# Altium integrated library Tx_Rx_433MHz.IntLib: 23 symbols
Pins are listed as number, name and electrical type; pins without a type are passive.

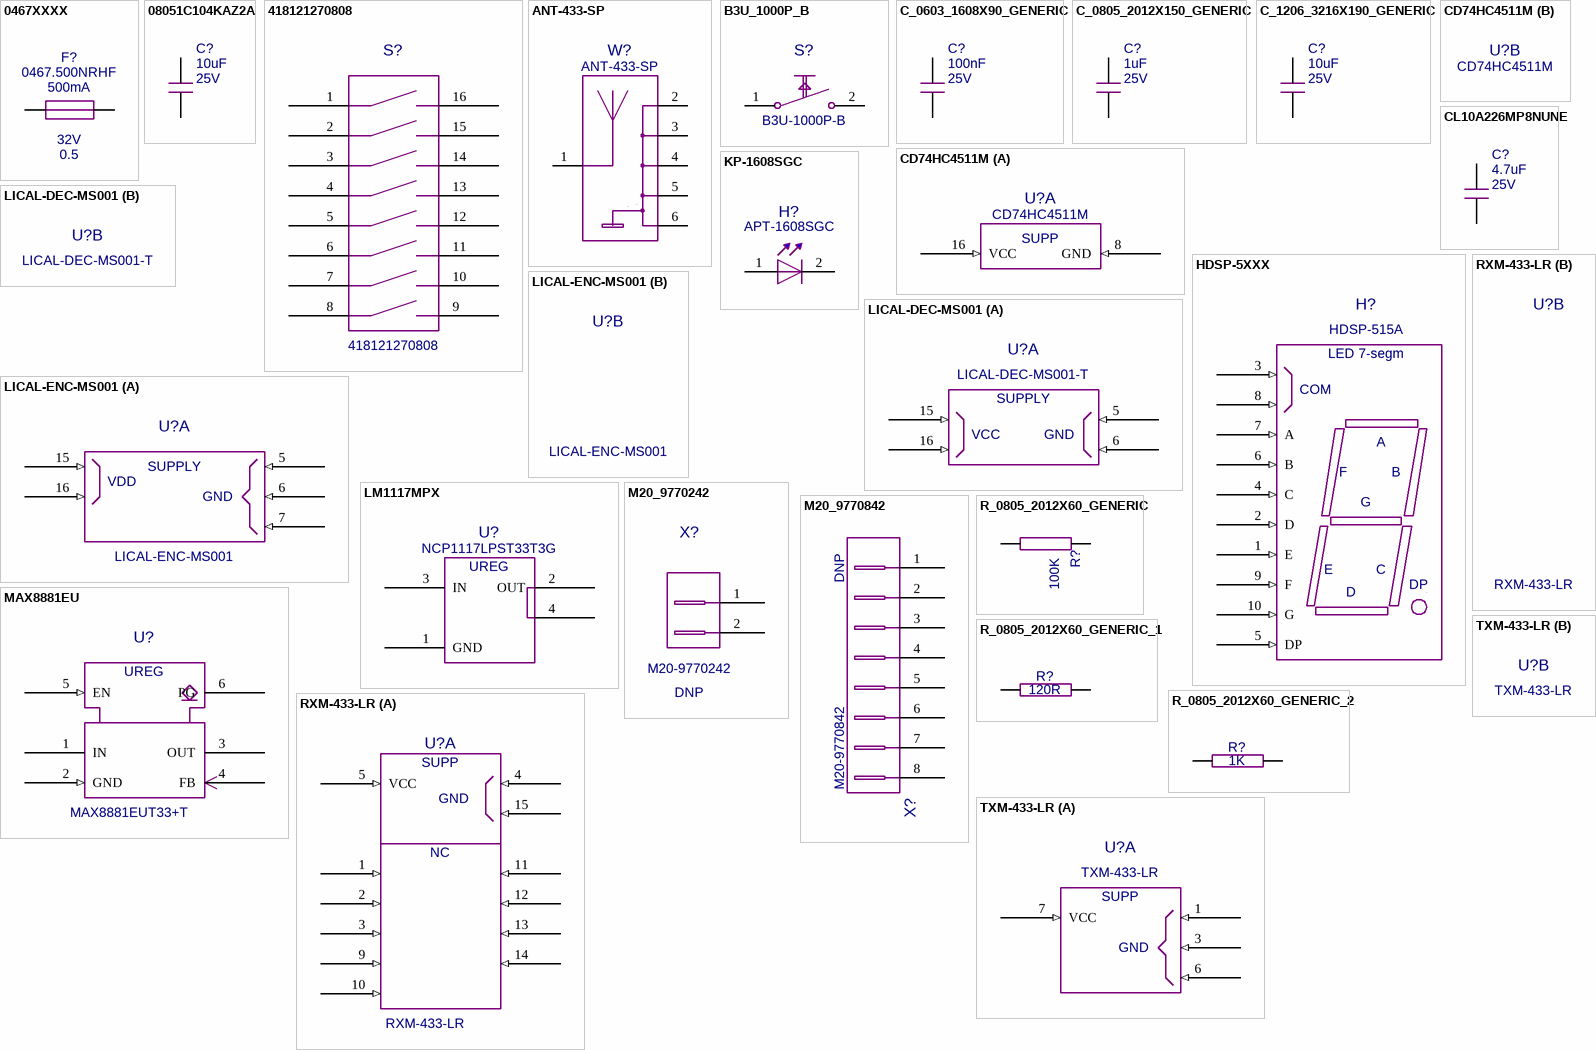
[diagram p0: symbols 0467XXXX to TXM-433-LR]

## 0467XXXX
designator F?  value 500mA  Current: 0.5  MPN: 0467.500NRHF  Voltage: 32V  (hidden comment: 0467XXXX)
Thin film 0603 fuse very fast acting; Manufacturer: LITTELFUSE; Part Name: Thin film 0603 very fast acting; Cell Name: RESC1608X60N_0603_GENERIC; CmpIndex: 18; Level: STD; Max Temp: +90; Min Temp: -55; Ref Designator: F200; SymIndex: 25; Valid: -1
footprint RESC1608X60N_0603_GENERIC
pins: 1 A, 2 B

## 08051C104KAZ2A
designator C?  value 10uF  Voltage: 25V  (hidden comment: 08051C104KAZ2A)
10uF 25V 10%; Manufacturer: AVX; MPN: 08053D106KAT2A; Part Name: 0805 chip 100nF 10% 100V X7R; Parts: 1; Capacitance: 10000000; Cell Name: CAPC2013X140N_AVX; CmpIndex: 15; Dielectric: X5R; DXDB_LIBNAME: Capacitor; Level: STD; Ref Designator: C207; SymIndex: 23; Tolerance: 10; Type: Ceramic; Valid: 0
footprint CAPC2013X140N_AVX
pins: 1 P, 2 M

## 418121270808
designator S?
Dip Switch SPST 8 Position Surface Mount Slide (Standard) Actuator 25mA 24VDC; Manufacturer: WURTH ELEKTRONIK; Cell Name: WE_418121270808; CmpIndex: 1; Contacts: 8; Level: STD; Max Temp: 85; Min Temp: -40; Ref Designator: S100; SymIndex: 7; Valid: -1; Voltage: 24
footprint WE_418121270808
pins: 1 S1_1, 2 S2_1, 3 S3_1, 4 S4_1, 5 S5_1, 6 S6_1, 7 S7_1, 8 S8_1, 9 S8_2, 10 S7_2, 11 S6_2, 12 S5_2, 13 S4_2, 14 S3_2, 15 S2_2, 16 S1_2

## ANT-433-SP
designator W?
433MHz 50 Ohm Antenna module; Manufacturer: Linx Technologies; Cell Name: LINX_ANT-433-SP; CmpIndex: 93; Level: STD; Max Temp: 130; Min Temp: -40; Quality: Q2; Ref Designator: W200; SymIndex: 37; Valid: 0
footprint LINX_ANT-433-SP
pins: 1 ANT, 2 GND1, 3 GND2, 4 GND3, 5 GND4, 6 GND5

## B3U_1000P_B
designator S?  MPN: B3U-1000P-B  (hidden comment: B3U_1000P_B)
Ultra-small Tactile Switch; Manufacturer: OMRON; Cell Name: OMRON_B3U_1000P_B; CmpIndex: 1; Contacts: 2; Level: STD; Max Temp: 0; Ref Designator: S201; SymIndex: 8
footprint OMRON_B3U_1000P_B
pins: 1 S1, 2 S2

## C_0603_1608X90_GENERIC
designator C?  value 100nF  Voltage: 25V  (hidden comment: C_0603_1608X90_GENERIC)
100nF 25V 10%; Manufacturer: MURATA; MPN: GRM188R71E104KA01D; Part Name: Ceramic chip capacitor 0603-1608x90, generic; Parts: 1; Capacitance: 100000; Cell Name: CAPC1608X90N_0603_GENERIC; CmpIndex: 81; Dielectric: X7R; DXDB_LIBNAME: Capacitor; Level: STD; Ref Designator: C203; SymIndex: 23; Tolerance: 10; Type: Ceramic; Valid: -1
footprint CAPC1608X90N_0603_GENERIC
pins: 1 P, 2 M

## C_0805_2012X150_GENERIC
designator C?  value 1uF  Voltage: 25V  (hidden comment: C_0805_2012X150_GENERIC)
1µF 25V 10%; Manufacturer: AVX; MPN: 08053C105K4Z2A; Part Name: Ceramic chip capacitor 0805-2012x150, generic; Parts: 1; Capacitance: 1000000; Cell Name: CAPC2012X150N_0805_GENERIC; CmpIndex: 14; Dielectric: X7R; DXDB_LIBNAME: Capacitor; Level: STD; Ref Designator: C103; SymIndex: 23; Tolerance: 10; Type: Ceramic; Valid: -1
footprint CAPC2012X150N_0805_GENERIC
pins: 1 P, 2 M

## C_1206_3216X190_GENERIC
designator C?  value 10uF  Voltage: 25V  (hidden comment: C_1206_3216X190_GENERIC)
10uF 25V 10%; Manufacturer: AVX; MPN: 12063C106KAT2A; Part Name: Cheramic chip capacitor 1206-3216x190, generic; Parts: 1; Capacitance: 10000000; Cell Name: CAPC3216X190N_1206_GENERIC; CmpIndex: 33; Dielectric: X7R; DXDB_LIBNAME: Capacitor; Level: STD; Max Temp: +125; Min Temp: -55; Ref Designator: C205; SymIndex: 23; Tolerance: 10; Type: Ceramic; Valid: -1
footprint CAPC3216X190N_1206_GENERIC
pins: 1 P, 2 M

## CD74HC4511M
designator U?
Leddriver BCD to 7 segment 1 Digit; Manufacturer: TEXAS INSTRUMENTS; Parts: 1; Cell Name: SOIC127P600X175-16N; CmpIndex: 75; DXDB_LIBNAME: IC Generic; Level: STD; Max Temp: 125; Min Temp: -55; Ref Designator: U203; SymIndex: 32; Valid: 0
footprint SOIC127P600X175-16N
part A pins: 8 GND (in), 16 VCC (in)

## CL10A226MP8NUNE
designator C?  value 4.7uF  Voltage: 25V  (hidden comment: CL10A226MP8NUNE)
4.7uF 25V 10%; Alternate Manufacturer: SAMSUNG; Alternate MPN: CL10A475KA8NQNC; Manufacturer: AVX; MPN: 06033D475KAT2A; Part Name: CAP 22uF 10V 0603 X5R; Parts: 1; Capacitance: 4700000; Cell Name: CAPC1608X105N; CmpIndex: 15; Dielectric: X5R; DXDB_LIBNAME: Capacitor; Level: STD; Ref Designator: C104; SymIndex: 23; Tolerance: 10; Type: Ceramic; Valid: 0
footprint CAPC1608X105N
pins: 1 P, 2 M

## HDSP-5XXX
designator H?  MPN: HDSP-515A  (hidden comment: HDSP-5XXX)
7 Segment Display Module Red, 1,85V, 20mA. THT; Manufacturer: BROADCOM; Part Name: Single Digit LED Numeric Display, Blue color; Cell Name: BROADCOM_HDSP-5XXX; CmpIndex: 66; DXDB_LIBNAME: Optical; Level: STD; Max Temp: 85; Min Temp: -25; Ref Designator: H201; SymIndex: 14; Valid: 0
footprint BROADCOM_HDSP-5XXX
pins: 1 E (in), 2 D (in), 3 COM1 (in), 4 C (in), 5 DP (in), 6 B (in), 7 A (in), 8 COM2 (in), 9 F (in), 10 G (in)

## KP-1608SGC
designator H?  MPN: APT-1608SGC  (hidden comment: KP-1608SGC)
LED Green; Manufacturer: KINGBRIGHT; Part Name: SMD LED lamp, Green; Parts: 1; Cell Name: LEDC1608X110N; CmpIndex: 57; Current: 20mA; DXDB_LIBNAME: Diode; Level: STD; Ref Designator: H100; SymIndex: 29; Valid: -1
footprint LEDC1608X110N
pins: 1 A, 2 K

## LICAL-DEC-MS001
designator U?  MPN: LICAL-DEC-MS001-T  (hidden comment: LICAL-DEC-MS001)
MS Series Remote Controler Decoder, Low Voltage, Low Power; Manufacturer: LINX TECHNOLOGIES; Cell Name: SOP65P780X200-20N; CmpIndex: 8; DXDB_LIBNAME: IC Generic; Level: STD; Max Temp: 85; Min Temp: -40; Ref Designator: U201; SymIndex: 16; Valid: 0
footprint SOP65P780X200-20N
part A pins: 5 GND1 (in), 6 GND2 (in), 15 VCC1 (in), 16 VCC2 (in)

## LICAL-ENC-MS001
designator U?
MS Series Remote Controler Encoder, Low Voltage, Low Power; Manufacturer: LINX TECHNOLOGIES; Cell Name: SOP65P780X200-20N; CmpIndex: 6; DXDB_LIBNAME: IC Generic; Level: STD; Max Temp: 85; Min Temp: -40; Ref Designator: U101; SymIndex: 19; Valid: 0
footprint SOP65P780X200-20N
part A pins: 5 GND1 (in), 6 GND2 (in), 7 GND3 (in), 15 VDD1 (in), 16 VDD2 (in)

## LM1117MPX
designator U?  MPN: NCP1117LPST33T3G  (hidden comment: LM1117MPX)
3.3V/1A fixed regulator; Manufacturer: ON-SEMI; Part Name: 800mA Low-Dropout Linear Regulator, SOT223; Cell Name: SOT230P700X180-4N; CmpIndex: 10; DXDB_LIBNAME: IC Power; Level: STD; Ref Designator: U204; SymIndex: 36; Valid: -1; Vin Max: 18; Vin Min: -0.3; Vout Max: 3.365; Vout Min: 3.235
footprint SOT230P700X180-4N
pins: 1 GND, 2 OUT, 3 IN, 4 TAB

## M20_9770242
designator X?  MPN: M20-9770242  Place: DNP  (hidden comment: M20_9770242)
1x2 pin 2.54 mm pitch vertical header; Manufacturer: HARWIN; Part Name: STD_HEADER_1x2_2.54_THT; Cell Name: HARWIN_M20_9770242; CmpIndex: 11; DXDB_LIBNAME: Connector; Gender: male; Level: STD; Name: 9V in; Ref Designator: X201; SymIndex: 21; Valid: -1
footprint HARWIN_M20_9770242
pins: 1 P1, 2 P2

## M20_9770842
designator X?  MPN: M20-9770842  Place: DNP  (hidden comment: M20_9770842)
1x8 pin 2.54 mm pitch vertical header; Manufacturer: HARWIN; Part Name: STD_HEADER_1x8_2.54_THT; Cell Name: HARWIN_M20_9770842; CmpIndex: 9; DXDB_LIBNAME: Connector; Gender: male; Level: STD; Ref Designator: X200; SymIndex: 17; Valid: -1
footprint HARWIN_M20_9770842
pins: 1 P1, 2 P2, 3 P3, 4 P4, 5 P5, 6 P6, 7 P7, 8 P8

## MAX8881EU
designator U?  MPN: MAX8881EUT33+T  (hidden comment: MAX8881EU)
Low Dropout Linear Regulator with enable and power good, 3.3V, 6 pin SOT23; Manufacturer: MAXIM; Part Name: Low Dropout Linear Regulator, 6 pin SOT23; Cell Name: SOT95P280X100-6N; CmpIndex: 8; DXDB_LIBNAME: IC Power; Level: STD; Max Temp: 85; Min Temp: -40; Output Current: 0.20A; Quality: Q2; Ref Designator: U102; SymIndex: 20; Valid: 0; Vin Max: 12V; Vin Min: 4.3V; Vout Max: 3.3
footprint SOT95P280X100-6N
pins: 1 IN, 2 GND (in), 3 OUT, 4 FB, 5 EN (in), 6 PG

## R_0805_2012X60_GENERIC
designator R?  value 100K  (hidden comment: R_0805_2012X60_GENERIC)
0.125W 5% 100K 50V; Manufacturer: YAGEO; MPN: RC0805JR-07100KL; Part Name: resistor_0805-2012x60 generic; Cell Name: RESC2012X60N_0805_GENERIC; CmpIndex: 91; DXDB_LIBNAME: Resistor_0805; Level: STD; Ref Designator: R230; SymIndex: 28; Valid: -1
footprint RESC2012X60N_0805_GENERIC
pins: 1 P, 2 M

## R_0805_2012X60_GENERIC_1
designator R?, comment value 120R  (hidden comment: R_0805_2012X60_GENERIC)
0.125W 5% 120R 50V; Manufacturer: YAGEO; MPN: RC0805JR-07120RL; Part Name: resistor_0805-2012x60 generic; Cell Name: RESC2012X60N_0805_GENERIC; CmpIndex: 74; DXDB_LIBNAME: Resistor_0805; Level: STD; Ref Designator: R215; SymIndex: 28; Valid: -1
footprint RESC2012X60N_0805_GENERIC
pins: 1 P, 2 M

## R_0805_2012X60_GENERIC_2
designator R?, comment value 1K  (hidden comment: R_0805_2012X60_GENERIC)
Resistor_1K_1%_0805; Manufacturer: MULTICOMP; MPN: MCPWR05FTEW1001; Part Name: resistor_0805-2012x60 generic; Cell Name: RESC2012X60N_0805_GENERIC; CmpIndex: 50; DXDB_LIBNAME: Resistor_0805; Level: STD; Ref Designator: R224; SymIndex: 28; Tolerance: 1%; Valid: -1
footprint RESC2012X60N_0805_GENERIC
pins: 1 P, 2 M

## RXM-433-LR
designator U?
LR Series Receiver, Low Voltage, Low Power; Manufacturer: Linx Technologies; Cell Name: LINX_RXM-433-LR; CmpIndex: 4; DXDB_LIBNAME: Module; Level: STD; Max Temp: 70; Min Temp: -40; Quality: Q2; Ref Designator: U200; SymIndex: 13; Valid: 0
footprint LINX_RXM-433-LR
part A pins: 1 NC1 (in), 2 NC2 (in), 3 NC3 (in), 4 GND1 (in), 5 VCC (in), 9 NC4 (in), 10 NC5 (in), 11 NC6 (in), 12 NC7 (in), 13 NC8 (in), 14 NC9 (in), 15 GND2 (in)

## TXM-433-LR
designator U?
LR Series Transmitter, Low Voltage, Low Power; Manufacturer: Linx Technologies; Cell Name: LINX_TXM-433-LR; CmpIndex: 4; DXDB_LIBNAME: Module; Level: STD; Max Temp: 85; Min Temp: -40; Quality: Q2; Ref Designator: U100; SymIndex: 10; Valid: 0
footprint LINX_TXM-433-LR
part A pins: 1 GND1 (in), 3 GND2 (in), 6 GND3 (in), 7 VCC (in)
